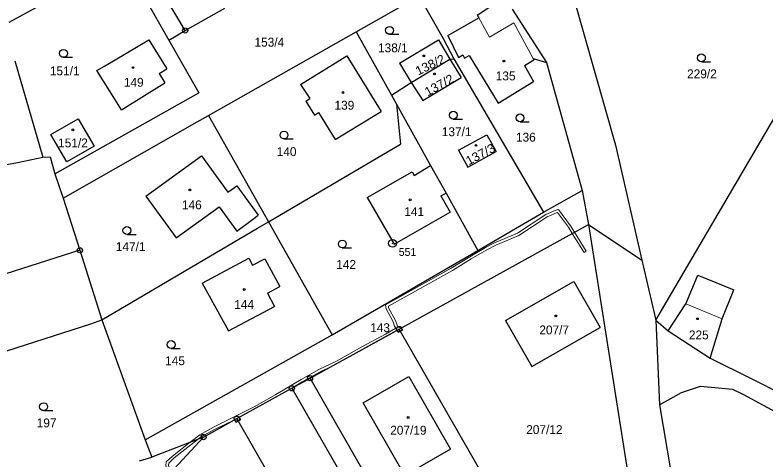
# Model space of a CAD drawing. Extents: x -633485 to -630509, y -1112692 to -1108818.
# Drawn here: x -631887.2 to -631743.5, y -1111932.7 to -1111847.5 of the extents above; entities that cross this region are included whole.
import ezdxf
from ezdxf.enums import TextEntityAlignment as Align

# ---------------------------------------------------------------- set-up
doc = ezdxf.new("R2010")
doc.units = 0
doc.header["$LTSCALE"] = 0.68
for name, color, linetype, lineweight in [('1', 7, 'Continuous', 25), ('13', 7, 'Continuous', 13), ('3', 7, 'Continuous', 25), ('4', 7, 'Continuous', 13), ('5', 7, 'Continuous', 25), ('8', 7, 'Continuous', 25)]:
    doc.layers.add(name, color=color, linetype=linetype, lineweight=lineweight)
doc.layers.add('2', color=7, linetype='Continuous')

msp = doc.modelspace()

# ---------------------------------------------------------------- linework, layer by layer
at = {"layer": '1'}
for p, q in [((-631854.56, -1111850.42), (-631863.52, -1111835.32)), ((-631888.32, -1111848.82), (-631866.42, -1111836.9)), ((-631866.42, -1111836.9), (-631857.68, -1111852.27)), ((-631755.72, -1111891.12), (-631726.57, -1111841.36)), ((-631780.53, -1111842.73), (-631772.13, -1111872.41)), ((-631821.81, -1111850.68), (-631809.73, -1111843.82)), ((-631809.73, -1111843.82), (-631805.13, -1111851.95)), ((-631798.6, -1111847.51), (-631794.26, -1111844.56)), ((-631854.56, -1111850.42), (-631846.97, -1111846.13)), ((-631791.93, -1111846.33), (-631785.34, -1111856.57)), ((-631798.6, -1111847.51), (-631798.3, -1111848.03)), ((-631804.22, -1111851.41), (-631798.3, -1111848.03)), ((-631857.68, -1111852.27), (-631854.56, -1111850.42)), ((-631850.07, -1111866.72), (-631821.81, -1111850.68)), ((-631821.81, -1111850.68), (-631815.03, -1111862.82)), ((-631870.05, -1111857.27), (-631861.55, -1111852.2)), ((-631861.55, -1111852.2), (-631858.09, -1111857.76)), ((-631857.68, -1111852.27), (-631851.92, -1111862.4)), ((-631813.48, -1111856.72), (-631806.03, -1111852.24)), ((-631806.03, -1111852.24), (-631803.82, -1111855.91)), ((-631805.13, -1111851.95), (-631803.1, -1111855.85)), ((-631804.22, -1111851.41), (-631802.19, -1111855.63)), ((-631802.19, -1111855.63), (-631801.36, -1111855.12)), ((-631801.36, -1111855.12), (-631801.01, -1111855.71)), ((-631887.21, -1111856.22), (-631881.84, -1111874.72)), ((-631832.49, -1111860.8), (-631823.6, -1111855.29)), ((-631823.6, -1111855.29), (-631817.04, -1111865.93)), ((-631811.27, -1111860.39), (-631803.82, -1111855.91)), ((-631803.82, -1111855.91), (-631803.1, -1111855.85)), ((-631803.82, -1111855.91), (-631801.69, -1111859.46)), ((-631803.1, -1111855.85), (-631785.92, -1111885.27)), ((-631801.01, -1111855.71), (-631800.15, -1111855.19)), ((-631800.15, -1111855.19), (-631794.6, -1111864.33)), ((-631789.54, -1111857.12), (-631787.73, -1111856.04)), ((-631787.87, -1111855.77), (-631787.73, -1111856.04)), ((-631787.87, -1111855.77), (-631785.34, -1111856.57)), ((-631785.34, -1111856.57), (-631778.52, -1111881.09)), ((-631859.53, -1111858.69), (-631858.09, -1111857.76)), ((-631813.48, -1111856.72), (-631811.27, -1111860.39)), ((-631789.54, -1111857.12), (-631787.82, -1111860.22)), ((-631859.53, -1111858.69), (-631858.44, -1111860.45)), ((-631809.05, -1111863.87), (-631801.69, -1111859.46)), ((-631866.8, -1111865.65), (-631858.44, -1111860.45)), ((-631832.49, -1111860.8), (-631830.65, -1111863.48)), ((-631815.03, -1111862.82), (-631811.27, -1111860.39)), ((-631811.27, -1111860.39), (-631809.05, -1111863.87)), ((-631794.6, -1111864.33), (-631787.82, -1111860.22)), ((-631866.8, -1111865.65), (-631869.03, -1111862.06)), ((-631879.52, -1111877.88), (-631851.92, -1111862.4)), ((-631831.42, -1111863.96), (-631830.65, -1111863.48)), ((-631815.03, -1111862.82), (-631814.06, -1111864.53)), ((-631831.42, -1111863.96), (-631829.8, -1111866.65)), ((-631814.06, -1111864.53), (-631813.28, -1111872.18)), ((-631814.06, -1111864.53), (-631807.53, -1111876.31)), ((-631829.8, -1111866.65), (-631829, -1111866.15)), ((-631829, -1111866.15), (-631825.8, -1111871.34)), ((-631825.8, -1111871.34), (-631817.04, -1111865.93)), ((-631877.97, -1111882.58), (-631852.25, -1111867.96)), ((-631852.25, -1111867.96), (-631850.07, -1111866.72)), ((-631850.07, -1111866.72), (-631838.61, -1111887.09)), ((-631802.17, -1111873.37), (-631796.75, -1111870.4)), ((-631796.75, -1111870.4), (-631794.99, -1111873.64)), ((-631838.61, -1111887.09), (-631813.28, -1111872.18)), ((-631772.13, -1111872.41), (-631767.07, -1111894.41)), ((-631802.17, -1111873.37), (-631800.43, -1111876.59)), ((-631800.43, -1111876.59), (-631794.99, -1111873.64)), ((-631886.67, -1111875.7), (-631881.84, -1111874.72)), ((-631881.84, -1111874.72), (-631880.43, -1111874.61)), ((-631880.43, -1111874.61), (-631879.52, -1111877.88)), ((-631862.08, -1111882.16), (-631851.42, -1111874.46)), ((-631851.42, -1111874.46), (-631846.4, -1111881.42)), ((-631908.88, -1111879.83), (-631886.67, -1111875.7)), ((-631810.69, -1111878.19), (-631807.53, -1111876.31)), ((-631807.53, -1111876.31), (-631804.54, -1111881.62)), ((-631879.52, -1111877.88), (-631877.97, -1111882.58)), ((-631819.67, -1111882.42), (-631811.07, -1111877.52)), ((-631811.07, -1111877.52), (-631810.69, -1111878.19)), ((-631846.4, -1111881.42), (-631845.12, -1111880.5)), ((-631845.12, -1111880.5), (-631844.7, -1111880.19)), ((-631844.7, -1111880.19), (-631840.6, -1111885.84)), ((-631862.08, -1111882.16), (-631856.3, -1111890.17)), ((-631819.67, -1111882.42), (-631814.52, -1111891.4)), ((-631805.58, -1111882.13), (-631804.54, -1111881.62)), ((-631805.58, -1111882.13), (-631803.79, -1111885.25)), ((-631804.54, -1111881.62), (-631798.46, -1111892.61)), ((-631785.92, -1111885.27), (-631778.52, -1111881.09)), ((-631778.52, -1111881.09), (-631777.31, -1111887.62)), ((-631877.97, -1111882.58), (-631874.74, -1111892.53)), ((-631856.3, -1111890.17), (-631848.04, -1111884.21)), ((-631848.04, -1111884.21), (-631844.65, -1111888.9)), ((-631814.52, -1111891.4), (-631803.79, -1111885.25)), ((-631798.46, -1111892.61), (-631785.92, -1111885.27)), ((-631844.65, -1111888.9), (-631841.64, -1111886.62)), ((-631841.64, -1111886.62), (-631840.6, -1111885.84)), ((-631840.68, -1111888.31), (-631838.61, -1111887.09)), ((-631838.61, -1111887.09), (-631826.43, -1111908.75)), ((-631777.31, -1111887.62), (-631767.07, -1111894.41)), ((-631777.31, -1111887.62), (-631768.08, -1111945.95)), ((-631870.51, -1111905.87), (-631840.68, -1111888.31)), ((-631874.74, -1111892.53), (-631938.19, -1111912.84)), ((-631874.74, -1111892.53), (-631870.51, -1111905.87)), ((-631764.4, -1111905.93), (-631755.72, -1111891.12)), ((-631826.43, -1111908.75), (-631798.46, -1111892.61)), ((-631851.33, -1111898.82), (-631842.35, -1111894.08)), ((-631842.35, -1111894.08), (-631841.64, -1111895.41)), ((-631841.64, -1111895.41), (-631839.29, -1111894.16)), ((-631839.29, -1111894.16), (-631836.46, -1111899.48)), ((-631767.07, -1111894.41), (-631764.4, -1111905.93)), ((-631758.63, -1111902.82), (-631756.3, -1111897.33)), ((-631756.3, -1111897.33), (-631749.43, -1111900.15)), ((-631851.33, -1111898.82), (-631846.24, -1111907.98)), ((-631838.81, -1111900.73), (-631836.46, -1111899.48)), ((-631793.18, -1111905.99), (-631780.09, -1111898.5)), ((-631780.09, -1111898.5), (-631775.04, -1111907.32)), ((-631838.81, -1111900.73), (-631837.44, -1111903.29)), ((-631751.69, -1111905.66), (-631749.43, -1111900.15)), ((-631846.24, -1111907.98), (-631837.44, -1111903.29)), ((-631762.01, -1111907.98), (-631758.63, -1111902.82)), ((-631901.48, -1111915.84), (-631872.64, -1111906.66)), ((-631872.64, -1111906.66), (-631870.51, -1111905.87)), ((-631870.51, -1111905.87), (-631862.24, -1111928.87)), ((-631793.18, -1111905.99), (-631788.12, -1111914.81)), ((-631764.4, -1111905.93), (-631763.67, -1111922.15)), ((-631764.4, -1111905.93), (-631762.01, -1111907.98)), ((-631753.96, -1111913.23), (-631751.69, -1111905.66)), ((-631830.64, -1111917.06), (-631813.56, -1111907.63)), ((-631788.12, -1111914.81), (-631775.04, -1111907.32)), ((-631762.01, -1111907.98), (-631753.96, -1111913.23)), ((-631862.24, -1111928.87), (-631826.43, -1111908.75)), ((-631753.96, -1111913.23), (-631746.13, -1111917.13)), ((-631820.46, -1111921.76), (-631811.7, -1111916.74)), ((-631834.14, -1111918.99), (-631830.64, -1111917.06)), ((-631806.94, -1111958.37), (-631830.64, -1111917.06)), ((-631746.13, -1111917.13), (-631721.5, -1111929.39)), ((-631844.65, -1111924.8), (-631834.14, -1111918.99)), ((-631763.67, -1111922.15), (-631759.48, -1111919.76)), ((-631759.48, -1111919.76), (-631755.79, -1111918.58)), ((-631755.79, -1111918.58), (-631749.71, -1111919.16)), ((-631749.71, -1111919.16), (-631747.56, -1111920.18)), ((-631747.56, -1111920.18), (-631631.76, -1111983.66)), ((-631763.67, -1111922.15), (-631761.5, -1111934.97)), ((-631851.05, -1111928.33), (-631844.65, -1111924.8)), ((-631822.53, -1111963.35), (-631844.65, -1111924.8)), ((-631861.16, -1111939.24), (-631851.05, -1111928.33)), ((-631851.05, -1111928.33), (-631860.98, -1111932.17)), ((-631862.24, -1111928.87), (-631860.98, -1111932.17)), ((-631863.34, -1111932.89), (-631860.98, -1111932.17))]:
    msp.add_line(p, q, dxfattribs=at)
for points in [[(-631869.03, -1111862.06), (-631871.48, -1111858.12), (-631870.05, -1111857.27)], [(-631787.95, -1111952.3), (-631813.56, -1111907.63), (-631777.31, -1111887.62)], [(-631811.7, -1111916.74), (-631803.71, -1111930.68), (-631812.47, -1111935.7), (-631820.46, -1111921.76)], [(-631834.14, -1111918.99), (-631810.84, -1111959.61), (-631822.53, -1111963.35)]]:
    msp.add_lwpolyline(points, dxfattribs=at)
msp.add_lwpolyline([(-631880.28, -1111870.37), (-631875.05, -1111867.36), (-631872.03, -1111872.59), (-631877.27, -1111875.6)], close=True, dxfattribs=at)
at = {"layer": '13'}
for points in [[(-631825.58, -1111913.79), (-631828.95, -1111915.4), (-631832.36, -1111917.28), (-631837.22, -1111920.19), (-631841.36, -1111922.51), (-631844.9, -1111924.32), (-631849.14, -1111926.42), (-631851.77, -1111927.88), (-631853.64, -1111929.33), (-631852, -1111928.7), (-631851.49, -1111928.3), (-631848.94, -1111926.88), (-631845.09, -1111925.04), (-631844.21, -1111924.56), (-631834.14, -1111918.99), (-631832.12, -1111917.72), (-631828.71, -1111915.84), (-631826.72, -1111914.9), (-631814, -1111907.87), (-631813.11, -1111907.38), (-631813.26, -1111907.14), (-631813.58, -1111907.32), (-631813.79, -1111907.2), (-631813.97, -1111906.86), (-631814.27, -1111906.02), (-631815.58, -1111903.57), (-631815.61, -1111903.25), (-631803.36, -1111896.42), (-631799.77, -1111894.2), (-631796.73, -1111892.43), (-631795.06, -1111891.58), (-631790.62, -1111889.71), (-631785.21, -1111886.15), (-631783.4, -1111885.35), (-631783.22, -1111885.31), (-631781.14, -1111888.12), (-631780.39, -1111889.32), (-631779.95, -1111889.08), (-631780.72, -1111887.84), (-631783, -1111884.75), (-631783.56, -1111884.87), (-631785.45, -1111885.71), (-631790.86, -1111889.27), (-631795.28, -1111891.12), (-631796.99, -1111892.01), (-631800.03, -1111893.78), (-631803.6, -1111895.98), (-631816.15, -1111902.97), (-631816.06, -1111903.73), (-631814.73, -1111906.22), (-631814.43, -1111907.06), (-631814.23, -1111907.44), (-631816.17, -1111908.59), (-631820.69, -1111911.06)], [(-631780.39, -1111889.32), (-631778.12, -1111892.99), (-631777.7, -1111892.73), (-631779.95, -1111889.08)], [(-631814, -1111907.87), (-631813.73, -1111908.32), (-631813.3, -1111908.08), (-631813.56, -1111907.63)], [(-631813.11, -1111907.38), (-631813.56, -1111907.63), (-631813.3, -1111908.08), (-631812.85, -1111907.83)], [(-631844.21, -1111924.56), (-631845.09, -1111925.04), (-631844.81, -1111925.51), (-631843.93, -1111925.03)], [(-631857.66, -1111935.46), (-631857.28, -1111935.05), (-631857.77, -1111933.81), (-631857.73, -1111933.31), (-631856.7, -1111932.34), (-631852, -1111928.7), (-631853.64, -1111929.33), (-631857.02, -1111931.96), (-631858.21, -1111933.07), (-631858.29, -1111933.87)]]:
    msp.add_lwpolyline(points, close=True, dxfattribs=at)
at = {"layer": '3'}
for p, q in [((-631815.403, -1111851.16), (-631813.653, -1111851.16)), ((-631877.883, -1111855.57), (-631876.133, -1111855.57)), ((-631755.643, -1111856.42), (-631753.893, -1111856.42)), ((-631803.183, -1111867.4), (-631801.433, -1111867.4)), ((-631790.403, -1111867.91), (-631788.653, -1111867.91)), ((-631835.633, -1111871.21), (-631833.883, -1111871.21)), ((-631865.733, -1111889.5), (-631863.983, -1111889.5)), ((-631824.453, -1111892.09), (-631822.703, -1111892.09)), ((-631857.263, -1111911.36), (-631855.513, -1111911.36)), ((-631881.703, -1111923.27), (-631879.953, -1111923.27))]:
    msp.add_line(p, q, dxfattribs=at)
for centre in [(-631815.4029, -1111850.4098), (-631877.8829, -1111854.8198), (-631755.6429, -1111855.6698), (-631803.1829, -1111866.6498), (-631790.4029, -1111867.1598), (-631835.6329, -1111870.4598), (-631865.7329, -1111888.7498), (-631824.4529, -1111891.3398), (-631857.2629, -1111910.6098), (-631881.7029, -1111922.5198)]:
    msp.add_circle(centre, 0.75, dxfattribs=at)
at = {"layer": '4'}
for p, q in [((-631798.3, -1111848.03), (-631796.22, -1111851.69)), ((-631796.22, -1111851.69), (-631791.61, -1111848.97)), ((-631791.61, -1111848.97), (-631787.87, -1111855.77)), ((-631758.63, -1111902.82), (-631751.69, -1111905.66))]:
    msp.add_line(p, q, dxfattribs=at)
at = {"layer": '5'}
for centre in [(-631808.8568, -1111855.3092), (-631793.5168, -1111856.2792), (-631864.5668, -1111857.5392), (-631806.8068, -1111858.7592), (-631824.3268, -1111862.3192), (-631876.0768, -1111869.4492), (-631798.8368, -1111872.4492), (-631853.6568, -1111880.9792), (-631811.4468, -1111882.8792), (-631843.2468, -1111900.0692), (-631783.5268, -1111905.1292), (-631756.4068, -1111905.6492), (-631811.8468, -1111924.5892)]:
    msp.add_circle(centre, 0.175, dxfattribs=at)
at = {"layer": '8'}
for centre, radius in [((-631854.56, -1111850.4199), 0.5), ((-631854.56, -1111850.4199), 0.0303), ((-631814.83, -1111891.1998), 0.75), ((-631874.74, -1111892.5299), 0.5), ((-631874.74, -1111892.5299), 0.0303), ((-631814.83, -1111891.1998), 0.03), ((-631813.56, -1111907.6299), 0.5), ((-631813.56, -1111907.6299), 0.0303), ((-631830.64, -1111917.0599), 0.5), ((-631830.64, -1111917.0599), 0.0303), ((-631834.14, -1111918.9899), 0.5), ((-631834.14, -1111918.9899), 0.0303), ((-631844.65, -1111924.7999), 0.5), ((-631844.65, -1111924.7999), 0.0303), ((-631851.05, -1111928.3299), 0.5), ((-631851.05, -1111928.3299), 0.0303)]:
    msp.add_circle(centre, radius, dxfattribs=at)

# ---------------------------------------------------------------- texts
at = {"layer": '2'}
for s, p in [('153/4', (-631838.44, -1111853.515)), ('151/1', (-631877.65, -1111859.025)), ('229/2', (-631755.54, -1111859.585)), ('151/2', (-631876.07, -1111872.825)), ('207/19', (-631811.8, -1111927.875)), ('207/12', (-631785.74, -1111927.755))]:
    msp.add_text(s, height=1.7, dxfattribs=at).set_placement(p, align=Align.CENTER)
for s, p in [('138/1', (-631817.61, -1111854.605)), ('149', (-631866.31, -1111861.205)), ('135', (-631795.05, -1111859.985)), ('139', (-631825.95, -1111865.605)), ('137/1', (-631805.39, -1111870.675)), ('136', (-631791.18, -1111871.725)), ('140', (-631837.03, -1111874.495)), ('146', (-631855.19, -1111884.685)), ('141', (-631812.58, -1111885.995)), ('147/1', (-631867.86, -1111892.695)), ('142', (-631825.62, -1111896.105)), ('144', (-631845.17, -1111903.775)), ('143', (-631819.11, -1111908.225)), ('207/7', (-631786.7, -1111908.655)), ('225', (-631758.04, -1111909.615)), ('145', (-631858.41, -1111914.555)), ('197', (-631883.02, -1111926.465))]:
    msp.add_text(s, height=1.7, dxfattribs=at).set_placement(p)
at = {"layer": '2', "width": 1.05}
msp.add_text('138/2', height=1.7, rotation=26, dxfattribs=at).set_placement((-631807.2436, -1111857.7694), align=Align.CENTER)
for s, rotation, p in [('137/2', 29, (-631808.093, -1111863.081)), ('137/3', 28, (-631800.23, -1111876.295))]:
    msp.add_text(s, height=1.7, rotation=rotation, dxfattribs=at).set_placement(p)
at = {"layer": '8'}
msp.add_text('551', height=1.5, dxfattribs=at).set_placement((-631813.64, -1111893.615))

doc.saveas('drawing.dxf')
